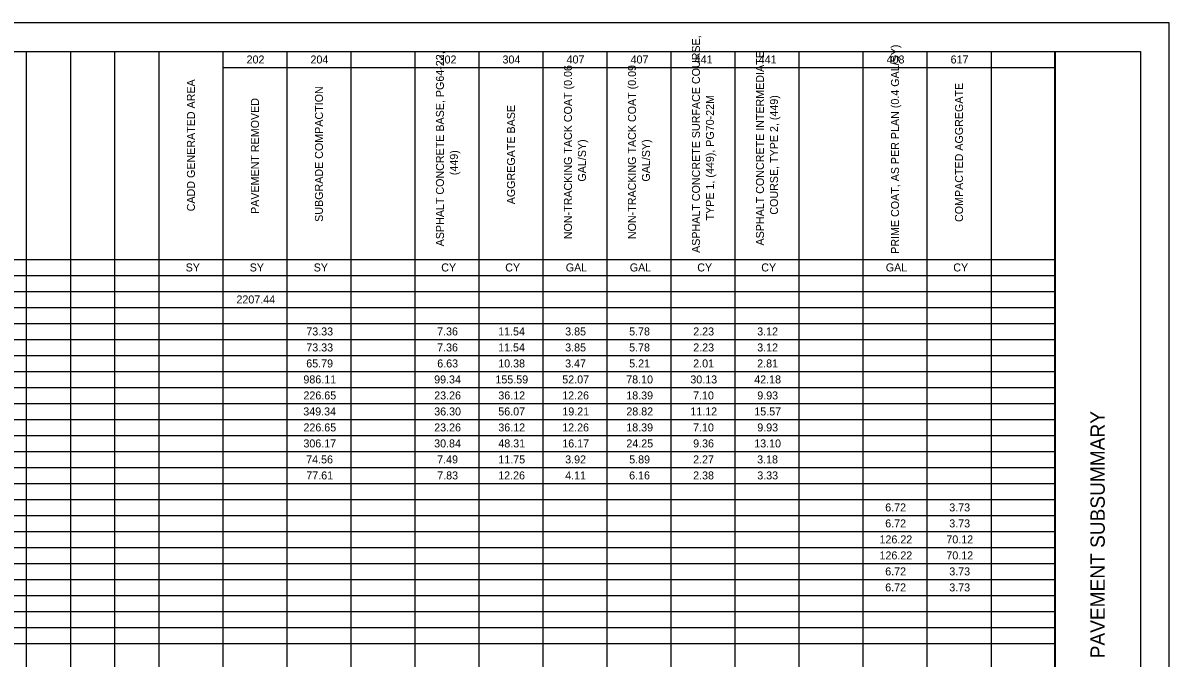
# Model space of a CAD drawing. Extents: x 0 to 34, y 0 to 22.
# Drawn here: x 13.94 to 34, y 10.88 to 22 of the extents above; entities that cross this region are included whole.
import ezdxf

# ---------------------------------------------------------------- set-up
doc = ezdxf.new("R2010")
doc.units = 0
for name, color, linetype in [('Default', 7, 'Continuous'), ('SH_Border', 7, 'Continuous'), ('SH_Cut_Line', 7, 'Continuous'), ('SH_Data', 7, 'Continuous')]:
    doc.layers.add(name, color=color, linetype=linetype)

msp = doc.modelspace()

# ---------------------------------------------------------------- linework, layer by layer
at = {"layer": 'SH_Border'}
msp.add_line((32, 0.5), (32, 21.5), dxfattribs=at)
msp.add_lwpolyline([(1.5, 21.5), (33.5, 21.5), (33.5, 0.5), (1.5, 0.5)], close=True, dxfattribs=at)
at = {"layer": 'SH_Cut_Line'}
msp.add_lwpolyline([(0, 0), (34, 0), (34, 22), (0, 22)], close=True, dxfattribs=at)
at = {"layer": 'SH_Data'}
for p, q in [((1.5, 21.5), (32.004, 21.5)), ((14.001, 21.5), (14.001, 1.06)), ((14.775, 21.5), (14.775, 1.06)), ((15.549, 21.5), (15.549, 1.06)), ((16.324, 21.5), (16.324, 1.06)), ((17.444, 21.5), (17.444, 0.5)), ((18.564, 21.5), (18.564, 0.5)), ((19.684, 21.5), (19.684, 0.5)), ((20.804, 21.5), (20.804, 0.5)), ((21.924, 21.5), (21.924, 0.5)), ((23.044, 21.5), (23.044, 0.5)), ((24.164, 21.5), (24.164, 0.78)), ((25.284, 21.5), (25.284, 0.5)), ((26.404, 21.5), (26.404, 0.5)), ((27.524, 21.5), (27.524, 0.5)), ((28.644, 21.5), (28.644, 0.5)), ((29.764, 21.5), (29.764, 0.5)), ((30.884, 21.5), (30.884, 0.5)), ((32.004, 21.5), (32.004, 0.5)), ((17.444, 21.22), (32.004, 21.22)), ((1.5, 17.86), (32.004, 17.86)), ((1.5, 17.58), (32.004, 17.58)), ((1.5, 17.3), (32.004, 17.3)), ((1.5, 17.02), (32.004, 17.02)), ((1.5, 16.74), (32.004, 16.74)), ((1.5, 16.46), (32.004, 16.46)), ((1.5, 16.18), (32.004, 16.18)), ((1.5, 15.9), (32.004, 15.9)), ((1.5, 15.62), (32.004, 15.62)), ((1.5, 15.34), (32.004, 15.34)), ((1.5, 15.06), (32.004, 15.06)), ((1.5, 14.78), (32.004, 14.78)), ((1.5, 14.5), (32.004, 14.5)), ((1.5, 14.22), (32.004, 14.22)), ((1.5, 13.94), (32.004, 13.94)), ((1.5, 13.66), (32.004, 13.66)), ((1.5, 13.38), (32.004, 13.38)), ((1.5, 13.1), (32.004, 13.1)), ((1.5, 12.82), (32.004, 12.82)), ((1.5, 12.54), (32.004, 12.54)), ((1.5, 12.26), (32.004, 12.26)), ((1.5, 11.98), (32.004, 11.98)), ((1.5, 11.7), (32.004, 11.7)), ((1.5, 11.42), (32.004, 11.42)), ((1.5, 11.14), (32.004, 11.14))]:
    msp.add_line(p, q, dxfattribs=at)

# ---------------------------------------------------------------- texts
at = {"layer": 'Default'}
for s, p in [('ASPHALT CONCRETE SURFACE COURSE, ', (25.791, 17.975)), ('ASPHALT CONCRETE BASE, PG64-22, ', (21.311, 18.09)), ('ASPHALT CONCRETE INTERMEDIATE ', (26.911, 18.104)), ('PRIME COAT, AS PER PLAN (0.4 GAL/SY)', (29.274, 17.959)), ('NON-TRACKING TACK COAT (0.06 ', (23.551, 18.214)), ('NON-TRACKING TACK COAT (0.09 ', (24.671, 18.216)), ('CADD GENERATED AREA', (16.954, 18.703)), ('SUBGRADE COMPACTION', (19.194, 18.519)), ('COMPACTED AGGREGATE', (30.394, 18.516)), ('PAVEMENT REMOVED', (18.074, 18.657)), ('TYPE 1, (449), PG70-22M', (26.036, 18.543)), ('COURSE, TYPE 2, (449)', (27.156, 18.644)), ('AGGREGATE BASE', (22.554, 18.826)), ('GAL/SY)', (23.796, 19.223)), ('GAL/SY)', (24.916, 19.223)), ('(449)', (21.556, 19.335))]:
    msp.add_text(s, height=0.14, rotation=90, dxfattribs=at).set_placement(p)
for s, p in [('202', (17.858, 21.29)), ('204', (18.976, 21.29)), ('302', (21.218, 21.29)), ('304', (22.336, 21.29)), ('407', (23.457, 21.29)), ('407', (24.577, 21.29)), ('441', (25.698, 21.29)), ('441', (26.818, 21.29)), ('408', (29.057, 21.29)), ('617', (30.177, 21.29)), ('SY', (16.792, 17.65)), ('SY', (17.912, 17.65)), ('SY', (19.032, 17.65)), ('CY', (21.264, 17.65)), ('CY', (22.384, 17.65)), ('GAL', (23.443, 17.65)), ('GAL', (24.563, 17.65)), ('CY', (25.744, 17.65)), ('CY', (26.864, 17.65)), ('GAL', (29.043, 17.65)), ('CY', (30.224, 17.65)), ('2207.44', (17.68, 17.09)), ('73.33', (18.903, 16.53)), ('7.36', (21.192, 16.53)), ('11.54', (22.26, 16.53)), ('3.85', (23.433, 16.53)), ('5.78', (24.552, 16.53)), ('2.23', (25.674, 16.53)), ('3.12', (26.793, 16.53)), ('73.33', (18.903, 16.25)), ('7.36', (21.192, 16.25)), ('11.54', (22.26, 16.25)), ('3.85', (23.433, 16.25)), ('5.78', (24.552, 16.25)), ('2.23', (25.674, 16.25)), ('3.12', (26.793, 16.25)), ('65.79', (18.902, 15.97)), ('6.63', (21.194, 15.97)), ('10.38', (22.261, 15.97)), ('3.47', (23.432, 15.97)), ('5.21', (24.553, 15.97)), ('2.01', (25.673, 15.97)), ('2.81', (26.793, 15.97)), ('986.11', (18.852, 15.69)), ('99.34', (21.14, 15.69)), ('155.59', (22.212, 15.69)), ('52.07', (23.382, 15.69)), ('78.10', (24.501, 15.69)), ('30.13', (25.623, 15.69)), ('42.18', (26.741, 15.69)), ('226.65', (18.853, 15.41)), ('23.26', (21.141, 15.41)), ('36.12', (22.263, 15.41)), ('12.26', (23.381, 15.41)), ('18.39', (24.502, 15.41)), ('7.10', (25.671, 15.41)), ('9.93', (26.794, 15.41)), ('349.34', (18.85, 15.13)), ('36.30', (21.141, 15.13)), ('56.07', (22.262, 15.13)), ('19.21', (23.383, 15.13)), ('28.82', (24.503, 15.13)), ('11.12', (25.623, 15.13)), ('15.57', (26.742, 15.13)), ('226.65', (18.853, 14.85)), ('23.26', (21.141, 14.85)), ('36.12', (22.263, 14.85)), ('12.26', (23.381, 14.85)), ('18.39', (24.502, 14.85)), ('7.10', (25.671, 14.85)), ('9.93', (26.794, 14.85)), ('306.17', (18.852, 14.57)), ('30.84', (21.14, 14.57)), ('48.31', (22.263, 14.57)), ('16.17', (23.382, 14.57)), ('24.25', (24.503, 14.57)), ('9.36', (25.672, 14.57)), ('13.10', (26.741, 14.57)), ('74.56', (18.901, 14.29)), ('7.49', (21.193, 14.29)), ('11.75', (22.263, 14.29)), ('3.92', (23.433, 14.29)), ('5.89', (24.553, 14.29)), ('2.27', (25.672, 14.29)), ('3.18', (26.792, 14.29)), ('77.61', (18.903, 14.01)), ('7.83', (21.194, 14.01)), ('12.26', (22.261, 14.01)), ('4.11', (23.433, 14.01)), ('6.16', (24.552, 14.01)), ('2.38', (25.672, 14.01)), ('3.33', (26.794, 14.01)), ('6.72', (29.033, 13.45)), ('3.73', (30.154, 13.45)), ('6.72', (29.033, 13.17)), ('3.73', (30.154, 13.17)), ('126.22', (28.933, 12.89)), ('70.12', (30.103, 12.89)), ('126.22', (28.933, 12.61)), ('70.12', (30.103, 12.61)), ('6.72', (29.033, 12.33)), ('3.73', (30.154, 12.33)), ('6.72', (29.033, 12.05)), ('3.73', (30.154, 12.05))]:
    msp.add_text(s, height=0.14, dxfattribs=at).set_placement(p)
at = {"layer": 'SH_Data'}
msp.add_text('PAVEMENT SUBSUMMARY', height=0.25, rotation=90, dxfattribs=at).set_placement((32.875, 10.879))

doc.saveas('drawing.dxf')
